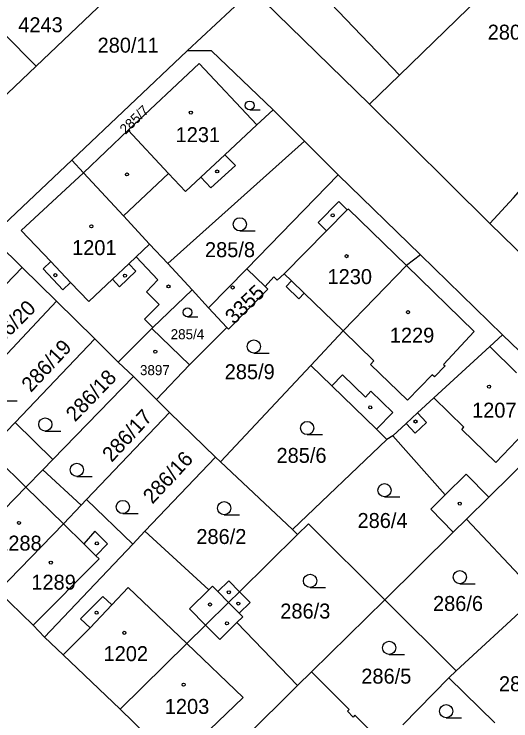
# Model space of a CAD drawing. Extents: x -679220 to -673243, y -1075091 to -1066557.
# Drawn here: x -676160.8 to -676104.3, y -1072146.6 to -1072066.3 of the extents above; entities that cross this region are included whole.
import ezdxf

# ---------------------------------------------------------------- set-up
doc = ezdxf.new("R2010")
doc.units = 0
for name, color, linetype in [('Hranice parcel', 7, 'Continuous'), ('Parcelní čísla', 7, 'Continuous'), ('Vnitřní kresba', 7, 'Continuous'), ('Značky budov', 7, 'Continuous'), ('Značky kultur', 7, 'Continuous')]:
    doc.layers.add(name, color=color, linetype=linetype)

msp = doc.modelspace()

# ---------------------------------------------------------------- linework, layer by layer
at = {"layer": 'Hranice parcel'}
for p, q in [((-676104.37, -1072060.94), (-676116.96, -1072073.18)), ((-676141.11, -1072070.44), (-676132.12, -1072062.03)), ((-676150.53, -1072064.78), (-676158.28, -1072072.17)), ((-676154.24, -1072082.84), (-676141.11, -1072070.44)), ((-676116.96, -1072073.18), (-676120.38, -1072076.5)), ((-676120.38, -1072076.5), (-676106.71, -1072090.05)), ((-676127.77, -1072080.68), (-676131.34, -1072077.11)), ((-676143.32, -1072094.61), (-676127.77, -1072080.68)), ((-676123.94, -1072084.5), (-676127.77, -1072080.68)), ((-676154.24, -1072082.84), (-676163.44, -1072091.53)), ((-676152.89, -1072084.29), (-676154.24, -1072082.84)), ((-676123.94, -1072084.5), (-676134.34, -1072095.2)), ((-676114.59, -1072093.59), (-676123.94, -1072084.5)), ((-676106.71, -1072090.05), (-676100.47, -1072096.13)), ((-676163.44, -1072091.53), (-676159.88, -1072095.04)), ((-676105.25, -1072102.7), (-676114.59, -1072093.59)), ((-676140.56, -1072097.58), (-676143.32, -1072094.61)), ((-676163.38, -1072098.67), (-676159.88, -1072095.04)), ((-676159.88, -1072095.04), (-676155.97, -1072098.88)), ((-676134.34, -1072095.2), (-676138.69, -1072099.64)), ((-676134.34, -1072095.2), (-676132.25, -1072097.2)), ((-676138.69, -1072099.64), (-676140.56, -1072097.58)), ((-676155.97, -1072098.88), (-676165.92, -1072109.45)), ((-676155.97, -1072098.88), (-676151.61, -1072103.17)), ((-676136.6, -1072101.86), (-676138.69, -1072099.64)), ((-676140.84, -1072106.11), (-676136.6, -1072101.86)), ((-676148.94, -1072105.8), (-676145.14, -1072101.98)), ((-676145.14, -1072101.98), (-676140.84, -1072106.11)), ((-676127.04, -1072106.18), (-676123.37, -1072102.26)), ((-676096.63, -1072111.09), (-676105.25, -1072102.7)), ((-676151.61, -1072103.17), (-676160.68, -1072112.67)), ((-676151.61, -1072103.17), (-676148.94, -1072105.8)), ((-676147.22, -1072107.44), (-676148.94, -1072105.8)), ((-676140.84, -1072106.11), (-676144.61, -1072110.04)), ((-676137.33, -1072117.12), (-676127.04, -1072106.18)), ((-676147.22, -1072107.44), (-676156.39, -1072116.87)), ((-676144.61, -1072110.04), (-676147.22, -1072107.44)), ((-676144.61, -1072110.04), (-676143.14, -1072111.53)), ((-676152.54, -1072121.4), (-676143.14, -1072111.53)), ((-676143.14, -1072111.53), (-676137.89, -1072116.59)), ((-676160.68, -1072112.67), (-676161.64, -1072113.68)), ((-676160.68, -1072112.67), (-676156.39, -1072116.87)), ((-676118.4, -1072114.6), (-676129.15, -1072124.84)), ((-676117.74, -1072114.18), (-676118.4, -1072114.6)), ((-676156.39, -1072116.87), (-676157.53, -1072118.04)), ((-676137.89, -1072116.59), (-676145.92, -1072125.03)), ((-676137.89, -1072116.59), (-676137.33, -1072117.12)), ((-676129.15, -1072124.84), (-676137.33, -1072117.12)), ((-676157.53, -1072118.04), (-676153.18, -1072122.07)), ((-676153.18, -1072122.07), (-676152.54, -1072121.4)), ((-676147.31, -1072126.49), (-676152.54, -1072121.4)), ((-676110.87, -1072125.11), (-676109.37, -1072123.64)), ((-676145.92, -1072125.03), (-676147.31, -1072126.49)), ((-676128.56, -1072125.39), (-676129.15, -1072124.84)), ((-676118.66, -1072132.8), (-676110.87, -1072125.11)), ((-676135.17, -1072131.89), (-676128.56, -1072125.39)), ((-676147.31, -1072126.49), (-676157.34, -1072137.04)), ((-676126.97, -1072140.99), (-676118.66, -1072132.8)), ((-676110.52, -1072140.89), (-676118.66, -1072132.8)), ((-676110.52, -1072140.89), (-676101.95, -1072132.98)), ((-676126.97, -1072140.99), (-676128.56, -1072142.56)), ((-676111.37, -1072141.68), (-676110.52, -1072140.89)), ((-676116.58, -1072147.02), (-676111.37, -1072141.68)), ((-676106.13, -1072146.78), (-676111.37, -1072141.68)), ((-676139.96, -1072153.8), (-676128.56, -1072142.56))]:
    msp.add_line(p, q, dxfattribs=at)
for points in [[(-676112.26, -1072052.87), (-676124.8, -1072065.03), (-676116.96, -1072073.18)], [(-676158.28, -1072072.17), (-676165.74, -1072064.68), (-676172.04, -1072058.35)], [(-676132.12, -1072062.03), (-676132.43, -1072064.73), (-676120.38, -1072076.5)], [(-676106.71, -1072090.05), (-676104.02, -1072087.14), (-676087.63, -1072068.46)], [(-676131.34, -1072077.11), (-676138.34, -1072070.44), (-676141.11, -1072070.44)], [(-676158.28, -1072072.17), (-676165.63, -1072079.13), (-676167.61, -1072079.88), (-676171.6, -1072083.85)], [(-676131.34, -1072077.11), (-676133.21, -1072078.82), (-676139.74, -1072071.87), (-676147.84, -1072079.45), (-676152.89, -1072084.29)], [(-676143.32, -1072094.61), (-676145.38, -1072092.39), (-676148.34, -1072089.19), (-676152.89, -1072084.29)], [(-676114.59, -1072093.59), (-676116.17, -1072094.82), (-676123.37, -1072102.26)], [(-676123.37, -1072102.26), (-676127.8, -1072097.97), (-676128.41, -1072098.6), (-676129.86, -1072097.2), (-676129.25, -1072096.58), (-676130.1, -1072095.76), (-676130.89, -1072096.49), (-676131.25, -1072096.11), (-676132.25, -1072097.2)], [(-676145.14, -1072101.98), (-676145.03, -1072101.88), (-676140.56, -1072097.58)], [(-676132.25, -1072097.2), (-676131.94, -1072097.5), (-676136.41, -1072102.06), (-676136.6, -1072101.86)], [(-676105.25, -1072102.7), (-676106.7, -1072104.03), (-676113.09, -1072109.86), (-676114.92, -1072111.56), (-676116.23, -1072112.77), (-676117.74, -1072114.18)], [(-676127.04, -1072106.18), (-676124.66, -1072108.5), (-676119.6, -1072113.43), (-676118.4, -1072114.6)], [(-676109.37, -1072123.64), (-676106.83, -1072121.16), (-676096.63, -1072111.09)], [(-676117.74, -1072114.18), (-676111.79, -1072120.9), (-676113.42, -1072122.5), (-676110.87, -1072125.11)], [(-676166.9, -1072127.63), (-676159.44, -1072120.01), (-676157.53, -1072118.04)], [(-676162.64, -1072131.84), (-676155.19, -1072124.18), (-676153.18, -1072122.07)], [(-676118.66, -1072132.8), (-676127.33, -1072124.18), (-676128.56, -1072125.39)], [(-676109.37, -1072123.64), (-676102.74, -1072130.71), (-676101.25, -1072132.29)], [(-676135.17, -1072131.89), (-676136.39, -1072130.65), (-676137.63, -1072131.87), (-676138.24, -1072131.25), (-676138.66, -1072131.66), (-676145.92, -1072125.03)], [(-676157.34, -1072137.04), (-676158.61, -1072135.71), (-676162.64, -1072131.84)], [(-676148.74, -1072145.24), (-676141.16, -1072137.78), (-676139.02, -1072135.68), (-676136.41, -1072133.11), (-676135.17, -1072131.89)], [(-676128.56, -1072142.56), (-676135.46, -1072135.4), (-676134.8, -1072134.75), (-676135.21, -1072134.34), (-676133.95, -1072133.13), (-676135.17, -1072131.89)], [(-676157.34, -1072137.04), (-676155.2, -1072139.07), (-676148.74, -1072145.24)], [(-676118.96, -1072149.46), (-676120.69, -1072147.75), (-676120.47, -1072147.52), (-676122.04, -1072145.93), (-676122.23, -1072146.15), (-676122.9, -1072145.47), (-676122.69, -1072145.28), (-676126.97, -1072140.99)], [(-676148.74, -1072145.24), (-676144.1, -1072149.74), (-676139.96, -1072153.8)]]:
    msp.add_lwpolyline(points, dxfattribs=at)
at = {"layer": 'Vnitřní kresba'}
for p, q in [((-676133.21, -1072078.82), (-676136.85, -1072082.23)), ((-676143.22, -1072084.37), (-676147.84, -1072079.45)), ((-676139.56, -1072084.78), (-676136.85, -1072082.23)), ((-676136.85, -1072082.23), (-676135.61, -1072083.46)), ((-676135.61, -1072083.46), (-676138.42, -1072086)), ((-676152.89, -1072084.29), (-676159.99, -1072090.86)), ((-676148.34, -1072089.19), (-676143.22, -1072084.37)), ((-676141.31, -1072086.41), (-676143.22, -1072084.37)), ((-676139.56, -1072084.78), (-676141.31, -1072086.41)), ((-676138.42, -1072086), (-676139.56, -1072084.78)), ((-676123.87, -1072087.56), (-676126.22, -1072089.95)), ((-676122.93, -1072088.49), (-676123.87, -1072087.56)), ((-676125.28, -1072090.88), (-676122.93, -1072088.49)), ((-676122.78, -1072088.4), (-676122.93, -1072088.49)), ((-676116.17, -1072094.82), (-676122.78, -1072088.4)), ((-676126.22, -1072089.95), (-676125.28, -1072090.88)), ((-676159.99, -1072090.86), (-676156.63, -1072094.37)), ((-676125.28, -1072090.88), (-676130.1, -1072095.76)), ((-676146.9, -1072093.83), (-676145.38, -1072092.39)), ((-676147.76, -1072094.64), (-676146.9, -1072093.83)), ((-676146.9, -1072093.83), (-676144.44, -1072096.43)), ((-676156.63, -1072094.37), (-676157.49, -1072095.19)), ((-676154.36, -1072096.74), (-676156.63, -1072094.37)), ((-676147.76, -1072094.64), (-676149.6, -1072096.38)), ((-676146.96, -1072095.48), (-676147.76, -1072094.64)), ((-676157.49, -1072095.19), (-676155.24, -1072097.59)), ((-676148.81, -1072097.23), (-676146.96, -1072095.48)), ((-676116.17, -1072094.82), (-676108.48, -1072102.33)), ((-676155.24, -1072097.59), (-676154.36, -1072096.74)), ((-676154.36, -1072096.74), (-676152.28, -1072098.91)), ((-676152.28, -1072098.91), (-676149.6, -1072096.38)), ((-676149.6, -1072096.38), (-676148.81, -1072097.23)), ((-676145.72, -1072097.8), (-676144.44, -1072096.43)), ((-676129.25, -1072096.58), (-676127.8, -1072097.97)), ((-676144.3, -1072099.26), (-676145.72, -1072097.8)), ((-676145.98, -1072100.91), (-676144.3, -1072099.26)), ((-676145.03, -1072101.88), (-676145.98, -1072100.91)), ((-676119.88, -1072105.64), (-676123.37, -1072102.26)), ((-676108.48, -1072102.33), (-676111.97, -1072106.07)), ((-676106.7, -1072104.03), (-676103.66, -1072107.03)), ((-676120.28, -1072106.06), (-676119.88, -1072105.64)), ((-676116.05, -1072110.14), (-676120.28, -1072106.06)), ((-676111.78, -1072106.23), (-676113, -1072107.47)), ((-676111.97, -1072106.07), (-676111.78, -1072106.23)), ((-676123.44, -1072107.26), (-676124.66, -1072108.5)), ((-676120.86, -1072109.77), (-676123.44, -1072107.26)), ((-676113.26, -1072107.25), (-676116.05, -1072110.14)), ((-676113, -1072107.47), (-676113.26, -1072107.25)), ((-676120.22, -1072109.11), (-676120.86, -1072109.77)), ((-676117.74, -1072111.52), (-676120.22, -1072109.11)), ((-676109.66, -1072113.21), (-676113.09, -1072109.86)), ((-676119.6, -1072113.43), (-676117.74, -1072111.52)), ((-676113.9, -1072112.66), (-676114.92, -1072111.56)), ((-676116.23, -1072112.77), (-676115.2, -1072113.87)), ((-676115.2, -1072113.87), (-676113.9, -1072112.66)), ((-676109.88, -1072113.44), (-676109.66, -1072113.21)), ((-676106.03, -1072117.2), (-676109.88, -1072113.44)), ((-676102.84, -1072113.87), (-676106.03, -1072117.2)), ((-676163.7, -1072115.84), (-676159.44, -1072120.01)), ((-676111.79, -1072120.9), (-676109.39, -1072118.55)), ((-676109.39, -1072118.55), (-676106.83, -1072121.16)), ((-676155.19, -1072124.18), (-676159.44, -1072120.01)), ((-676152.87, -1072126.46), (-676155.19, -1072124.18)), ((-676151.6, -1072125.02), (-676152.87, -1072126.46)), ((-676150.17, -1072126.45), (-676151.6, -1072125.02)), ((-676152.87, -1072126.46), (-676151.5, -1072127.8)), ((-676151.5, -1072127.8), (-676150.17, -1072126.45)), ((-676158.61, -1072135.71), (-676151.12, -1072128.17)), ((-676151.12, -1072128.17), (-676151.5, -1072127.8)), ((-676147.83, -1072131.42), (-676149.68, -1072133.39)), ((-676141.16, -1072137.78), (-676147.83, -1072131.42)), ((-676150.71, -1072132.42), (-676153.24, -1072134.97)), ((-676149.68, -1072133.39), (-676150.71, -1072132.42)), ((-676138.66, -1072131.66), (-676140.85, -1072133.82)), ((-676136.41, -1072133.11), (-676137.63, -1072131.87)), ((-676135.21, -1072134.34), (-676136.41, -1072133.11)), ((-676152.14, -1072136.01), (-676149.68, -1072133.39)), ((-676140.85, -1072133.82), (-676139.02, -1072135.68)), ((-676153.24, -1072134.97), (-676152.14, -1072136.01)), ((-676137.41, -1072137.32), (-676135.46, -1072135.4)), ((-676152.14, -1072136.01), (-676155.2, -1072139.07)), ((-676139.02, -1072135.68), (-676137.41, -1072137.32)), ((-676134.74, -1072143.91), (-676141.16, -1072137.78)), ((-676140.37, -1072149.29), (-676134.74, -1072143.91))]:
    msp.add_line(p, q, dxfattribs=at)
at = {"layer": 'Značky budov'}
for centre in [(-676140.697, -1072077.449), (-676137.707, -1072084.129), (-676147.957, -1072084.469), (-676124.567, -1072089.119), (-676152.007, -1072090.359), (-676122.997, -1072093.759), (-676156.107, -1072095.919), (-676148.187, -1072095.969), (-676143.237, -1072097.199), (-676135.947, -1072097.319), (-676116.017, -1072100.119), (-676144.737, -1072104.609), (-676106.797, -1072108.589), (-676120.307, -1072110.939), (-676115.157, -1072112.549), (-676110.127, -1072121.879), (-676160.237, -1072124.069), (-676151.387, -1072126.399), (-676156.617, -1072128.589), (-676136.377, -1072131.959), (-676138.517, -1072133.349), (-676135.307, -1072133.239), (-676151.417, -1072134.279), (-676136.587, -1072135.489), (-676148.267, -1072136.569), (-676141.517, -1072142.459)]:
    msp.add_circle(centre, 0.175, dxfattribs=at)
at = {"layer": 'Značky kultur'}
for p, q in [((-676134.005, -1072077.13), (-676132.833, -1072077.13)), ((-676135.133, -1072090.89), (-676133.383, -1072090.89)), ((-676141.075, -1072100.65), (-676139.903, -1072100.65)), ((-676133.533, -1072104.77), (-676131.783, -1072104.77)), ((-676162.173, -1072110.21), (-676160.423, -1072110.21)), ((-676157.243, -1072113.63), (-676155.493, -1072113.63)), ((-676127.473, -1072114.04), (-676125.723, -1072114.04)), ((-676153.663, -1072118.79), (-676151.913, -1072118.79)), ((-676118.683, -1072121.11), (-676116.933, -1072121.11)), ((-676148.433, -1072123.01), (-676146.683, -1072123.01)), ((-676136.903, -1072123.15), (-676135.153, -1072123.15)), ((-676127.143, -1072131.41), (-676125.393, -1072131.41)), ((-676110.113, -1072130.98), (-676108.363, -1072130.98)), ((-676118.143, -1072139.02), (-676116.393, -1072139.02)), ((-676111.673, -1072146.22), (-676109.923, -1072146.22))]:
    msp.add_line(p, q, dxfattribs=at)
for centre, radius in [((-676134.005, -1072076.627), 0.502), ((-676135.133, -1072090.14), 0.75), ((-676141.075, -1072100.147), 0.502), ((-676133.533, -1072104.02), 0.75), ((-676157.243, -1072112.88), 0.75), ((-676127.473, -1072113.29), 0.75), ((-676153.663, -1072118.04), 0.75), ((-676118.683, -1072120.36), 0.75), ((-676148.433, -1072122.26), 0.75), ((-676136.903, -1072122.4), 0.75), ((-676127.143, -1072130.66), 0.75), ((-676110.113, -1072130.23), 0.75), ((-676118.143, -1072138.27), 0.75), ((-676111.673, -1072145.47), 0.75)]:
    msp.add_circle(centre, radius, dxfattribs=at)

# ---------------------------------------------------------------- texts
at = {"layer": 'Parcelní čísla'}
for s, height, p in [('4243', 1.7, (-676160.314, -1072068.31)), ('280/6', 1.7, (-676106.95, -1072069.15)), ('280/11', 1.7, (-676151.3, -1072070.63)), ('1231', 1.7, (-676142.43, -1072080.8)), ('1201', 1.7, (-676154.2, -1072093.64)), ('285/8', 1.7, (-676139.09, -1072093.87)), ('1230', 1.7, (-676125.16, -1072096.93)), ('1229', 1.7, (-676118.08, -1072103.59)), ('285/4', 1.14, (-676142.99, -1072103.199)), ('3897', 1.14, (-676146.48, -1072107.28)), ('285/9', 1.7, (-676136.85, -1072107.739)), ('1207', 1.7, (-676108.73, -1072112.11)), ('285/6', 1.7, (-676130.96, -1072117.249)), ('286/4', 1.7, (-676121.75, -1072124.65)), ('286/2', 1.7, (-676140.07, -1072126.47)), ('1288', 1.7, (-676162.71, -1072127.22)), ('1289', 1.7, (-676158.83, -1072131.66)), ('286/6', 1.7, (-676113.17, -1072134.08)), ('286/3', 1.7, (-676130.53, -1072134.94)), ('1202', 1.7, (-676150.62, -1072139.779)), ('286/5', 1.7, (-676121.32, -1072142.34)), ('286/8', 1.7, (-676105.67, -1072143.2)), ('1203', 1.7, (-676143.66, -1072145.779))]:
    msp.add_text(s, height=height, dxfattribs=at).set_placement(p)
for s, height, rotation, p in [('285/7', 1.14, 44, (-676148.114, -1072079.98)), ('3355', 1.7, 44, (-676135.809, -1072101.581)), ('286/20', 1.7, 45, (-676163.108, -1072104.731)), ('286/19', 1.7, 47, (-676158.878, -1072109.319)), ('286/18', 1.7, 46, (-676153.858, -1072112.67)), ('286/17', 1.7, 47, (-676149.698, -1072117.259)), ('286/16', 1.7, 47, (-676145.068, -1072122.009))]:
    msp.add_text(s, height=height, rotation=rotation, dxfattribs=at).set_placement(p)

doc.saveas('drawing.dxf')
